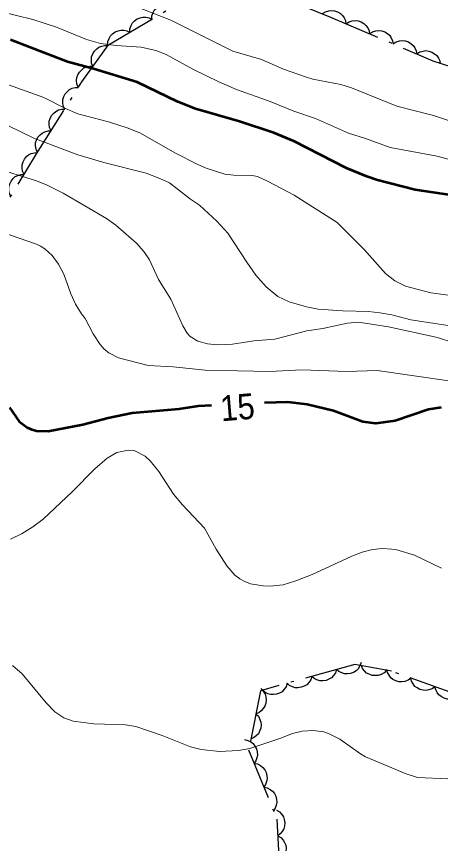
# Model space of a CAD drawing. Extents: x 356765 to 358572, y 5103174 to 5104650.
# Drawn here: x 357720.51 to 357745.32, y 5103497.3 to 5103545.71 of the extents above; entities that cross this region are included whole.
import ezdxf
from ezdxf.enums import TextEntityAlignment as Align

# ---------------------------------------------------------------- set-up
doc = ezdxf.new("R2010")
doc.units = 0
doc.header["$LTSCALE"] = 0.6
doc.linetypes.add('DOT_DASHED', pattern=[7.7, 5, -1.2, 0.3, -1.2])
for name, color, linetype, lineweight in [('1', 7, 'Continuous', 53), ('2', 7, 'Continuous', 13), ('44', 7, 'Continuous', 25)]:
    doc.layers.add(name, color=color, linetype=linetype, lineweight=lineweight)

msp = doc.modelspace()

# ---------------------------------------------------------------- linework, layer by layer
at = {"layer": '1'}
for points in [[(357748.85, 5103534.83), (357743.84, 5103535.57), (357741.64, 5103536.13), (357741.01, 5103536.34), (357739.82, 5103536.84), (357736.74, 5103538.42), (357735.57, 5103538.9), (357733.56, 5103539.57), (357730.98, 5103540.3), (357729.95, 5103540.71), (357727.56, 5103541.87), (357725.01, 5103542.65), (357723.49, 5103543.05), (357720.16, 5103544.34)], [(357745.37, 5103522.83), (357744.62, 5103522.7), (357742.67, 5103522.05), (357741.53, 5103521.88), (357740.78, 5103521.98), (357739.06, 5103522.63), (357737.51, 5103523), (357736.39, 5103523.13), (357735.02, 5103523.09)], [(357720.09, 5103522.83), (357720.65, 5103522.01), (357721.12, 5103521.65), (357721.4, 5103521.53), (357721.68, 5103521.45), (357722.36, 5103521.44), (357724.39, 5103521.82), (357725.86, 5103522.22), (357727.28, 5103522.51), (357730.02, 5103522.75), (357731.15, 5103522.93), (357731.92, 5103522.97)]]:
    msp.add_lwpolyline(points, dxfattribs=at)
at = {"layer": '2'}
for points in [[(357746.89, 5103539.26), (357744.92, 5103539.91), (357742.76, 5103540.46), (357740.11, 5103541.53), (357739.49, 5103541.74), (357737.84, 5103542.05), (357737.48, 5103542.16), (357736.14, 5103542.63), (357734.85, 5103543.19), (357733.17, 5103543.68), (357729.54, 5103545.5), (357726.78, 5103546.57)], [(357746.41, 5103537.18), (357745.12, 5103537.54), (357742.37, 5103538.05), (357740.94, 5103538.58), (357739.93, 5103538.88), (357738, 5103539.75), (357736.73, 5103540.17), (357735.35, 5103540.74), (357733.38, 5103541.43), (357732.35, 5103541.88), (357730.83, 5103542.63), (357729.27, 5103543.49), (357728.66, 5103543.73), (357727.8, 5103543.91), (357726.33, 5103544.01), (357725.42, 5103544.13), (357724.61, 5103544.36), (357722.85, 5103545.09), (357721.45, 5103545.54), (357719.55, 5103546)], [(357749.45, 5103528.92), (357744.75, 5103529.54), (357743.27, 5103529.93), (357742.64, 5103530.24), (357742.1, 5103530.66), (357740.86, 5103532.07), (357739.27, 5103533.65), (357736.75, 5103535.26), (357735.2, 5103536.08), (357734.61, 5103536.34), (357734.3, 5103536.4), (357733.23, 5103536.42), (357732.69, 5103536.49), (357731.61, 5103536.84), (357731.11, 5103537.05), (357729.81, 5103537.72), (357727.73, 5103538.91), (357726.99, 5103539.2), (357725.89, 5103539.54), (357724.1, 5103540.01), (357723.38, 5103540.32), (357722.11, 5103540.97), (357720.03, 5103541.72)], [(357746.93, 5103527.45), (357743.59, 5103527.96), (357742.47, 5103528.24), (357741.78, 5103528.36), (357741.1, 5103528.44), (357739.61, 5103528.48), (357738.16, 5103528.59), (357737.48, 5103528.72), (357736.46, 5103529.01), (357735.81, 5103529.32), (357735.11, 5103529.88), (357734.52, 5103530.58), (357733.98, 5103531.34), (357732.88, 5103533.03), (357732.23, 5103533.74), (357731.21, 5103534.67), (357730.69, 5103535.01), (357729.45, 5103535.97), (357728.9, 5103536.23), (357728.09, 5103536.54), (357725.61, 5103537.17), (357724.09, 5103537.61), (357721.52, 5103538.59), (357719.3, 5103539.67)], [(357746.11, 5103526.61), (357745.14, 5103526.92), (357742.28, 5103527.55), (357740.53, 5103527.82), (357739.87, 5103527.76), (357738.43, 5103527.45), (357737.5, 5103527.32), (357735.62, 5103526.82), (357734.4, 5103526.72), (357733.14, 5103526.54), (357732.29, 5103526.5), (357731.69, 5103526.55), (357731.12, 5103526.7), (357730.67, 5103526.99), (357730.5, 5103527.18), (357730.24, 5103527.61), (357729.53, 5103529.16), (357728.82, 5103530.32), (357728.28, 5103531.46), (357727.96, 5103531.95), (357727.53, 5103532.44), (357726.31, 5103533.5), (357725.77, 5103533.88), (357723.24, 5103535.37), (357722.29, 5103535.84), (357721.67, 5103536.09), (357719.14, 5103536.87)], [(357745.95, 5103524.37), (357741.61, 5103524.99), (357739.83, 5103524.93), (357737.2, 5103525.03), (357735.34, 5103524.94), (357731.55, 5103525.01), (357729.68, 5103525.2), (357728.21, 5103525.29), (357726.48, 5103525.73), (357725.9, 5103526.03), (357725.63, 5103526.24), (357725.41, 5103526.51), (357724.99, 5103527.13), (357724.52, 5103528.04), (357724.31, 5103528.3), (357723.96, 5103528.88), (357723.68, 5103529.48), (357723.28, 5103530.63), (357722.97, 5103531.21), (357722.6, 5103531.72), (357722.16, 5103532.11), (357721.91, 5103532.26), (357721.67, 5103532.38), (357719.64, 5103533.09)], [(357733.29, 5103513.01), (357733.04, 5103513.28), (357732.82, 5103513.55), (357732.19, 5103514.53), (357731.51, 5103515.76), (357730.22, 5103517.13), (357729.69, 5103517.76), (357728.83, 5103519.08), (357728.32, 5103519.71), (357728.03, 5103519.97), (357727.39, 5103520.3), (357727.06, 5103520.32), (357726.38, 5103520.19), (357725.81, 5103519.86), (357725.08, 5103519.24), (357723.77, 5103517.88), (357722.07, 5103516.29), (357721.45, 5103515.83), (357720.83, 5103515.45), (357720.15, 5103515.12)], [(357745.38, 5103513.42), (357743.8, 5103514.18), (357742.77, 5103514.5), (357742.47, 5103514.54), (357741.91, 5103514.58), (357741.34, 5103514.51), (357740.74, 5103514.36), (357740.13, 5103514.13), (357737.81, 5103513.04), (357736.85, 5103512.67), (357736.12, 5103512.45), (357735.36, 5103512.37), (357734.95, 5103512.38), (357734.2, 5103512.51), (357733.86, 5103512.63), (357733.57, 5103512.8), (357733.29, 5103513.01)], [(357745.76, 5103501.08), (357743.97, 5103501.17), (357743.31, 5103501.38), (357740.94, 5103502.38), (357740.63, 5103502.55), (357739.42, 5103503.41), (357738.81, 5103503.73), (357738.5, 5103503.83), (357737.86, 5103503.92), (357737.23, 5103503.87), (357736.65, 5103503.74), (357735.91, 5103503.44), (357734.17, 5103502.87), (357733.49, 5103502.74), (357732.39, 5103502.69), (357731.31, 5103502.8), (357730.68, 5103502.96), (357729.03, 5103503.63), (357727.49, 5103504.16), (357726.89, 5103504.25), (357725.02, 5103504.3), (357723.82, 5103504.46), (357723.27, 5103504.66), (357722.74, 5103505.01), (357722.24, 5103505.53), (357720.83, 5103507.23), (357720.27, 5103507.73)]]:
    msp.add_lwpolyline(points, dxfattribs=at)
at = {"layer": '44', "linetype": 'DOT_DASHED'}
for points in [[(357718.2, 5103531.95), (357721.68, 5103537.67), (357724.33, 5103541.89), (357725.88, 5103544.06), (357729.89, 5103546.42)], [(357736.33, 5103546.72), (357738.88, 5103545.68), (357744.88, 5103543.12), (357748.2, 5103542.05)], [(357746.38, 5103505.98), (357742.45, 5103507.39), (357740.31, 5103507.79), (357734.78, 5103506.24), (357734.09, 5103502.78), (357735.75, 5103498.72), (357735.91, 5103495.5)]]:
    msp.add_lwpolyline(points, dxfattribs=at)
at = {"layer": '44'}
for points in [[(357728.42, 5103545.55), (357728.43, 5103545.76), (357728.5, 5103545.95), (357728.58, 5103546.1), (357728.71, 5103546.22), (357728.86, 5103546.33), (357729.03, 5103546.4), (357729.19, 5103546.44), (357729.37, 5103546.43), (357729.55, 5103546.39), (357729.71, 5103546.32)], [(357738.41, 5103545.88), (357738.59, 5103545.99), (357738.78, 5103546.05), (357738.95, 5103546.07), (357739.12, 5103546.05), (357739.3, 5103545.99), (357739.46, 5103545.89), (357739.59, 5103545.78), (357739.68, 5103545.64), (357739.76, 5103545.47), (357739.79, 5103545.29)], [(357727.13, 5103544.79), (357727.14, 5103545), (357727.21, 5103545.19), (357727.29, 5103545.34), (357727.41, 5103545.46), (357727.56, 5103545.57), (357727.74, 5103545.64), (357727.9, 5103545.68), (357728.08, 5103545.67), (357728.26, 5103545.63), (357728.42, 5103545.55)], [(357739.79, 5103545.29), (357739.97, 5103545.4), (357740.16, 5103545.46), (357740.33, 5103545.48), (357740.5, 5103545.46), (357740.68, 5103545.4), (357740.84, 5103545.3), (357740.96, 5103545.19), (357741.06, 5103545.05), (357741.14, 5103544.88), (357741.17, 5103544.7)], [(357725.83, 5103544.03), (357725.85, 5103544.24), (357725.92, 5103544.43), (357726, 5103544.58), (357726.12, 5103544.7), (357726.27, 5103544.81), (357726.45, 5103544.88), (357726.61, 5103544.92), (357726.78, 5103544.91), (357726.96, 5103544.87), (357727.13, 5103544.79)], [(357741.17, 5103544.7), (357741.35, 5103544.82), (357741.54, 5103544.87), (357741.71, 5103544.89), (357741.88, 5103544.87), (357742.06, 5103544.81), (357742.22, 5103544.71), (357742.34, 5103544.61), (357742.44, 5103544.46), (357742.52, 5103544.29), (357742.55, 5103544.11)], [(357724.98, 5103542.8), (357724.9, 5103542.99), (357724.89, 5103543.19), (357724.9, 5103543.36), (357724.97, 5103543.52), (357725.06, 5103543.68), (357725.2, 5103543.82), (357725.32, 5103543.92), (357725.49, 5103543.98), (357725.67, 5103544.02), (357725.85, 5103544.02)], [(357742.55, 5103544.11), (357742.73, 5103544.23), (357742.92, 5103544.28), (357743.09, 5103544.31), (357743.26, 5103544.28), (357743.44, 5103544.22), (357743.6, 5103544.12), (357743.72, 5103544.02), (357743.82, 5103543.87), (357743.9, 5103543.7), (357743.93, 5103543.52)], [(357743.93, 5103543.52), (357744.11, 5103543.64), (357744.3, 5103543.69), (357744.47, 5103543.72), (357744.64, 5103543.69), (357744.82, 5103543.63), (357744.98, 5103543.53), (357745.1, 5103543.43), (357745.2, 5103543.28), (357745.28, 5103543.11), (357745.31, 5103542.94)], [(357724.11, 5103541.58), (357724.03, 5103541.77), (357724.02, 5103541.97), (357724.03, 5103542.14), (357724.09, 5103542.3), (357724.19, 5103542.46), (357724.32, 5103542.6), (357724.45, 5103542.7), (357724.62, 5103542.76), (357724.8, 5103542.8), (357724.98, 5103542.8)], [(357723.33, 5103540.29), (357723.24, 5103540.48), (357723.22, 5103540.68), (357723.22, 5103540.85), (357723.27, 5103541.02), (357723.36, 5103541.18), (357723.48, 5103541.33), (357723.6, 5103541.43), (357723.77, 5103541.51), (357723.94, 5103541.56), (357724.12, 5103541.56)], [(357722.53, 5103539.02), (357722.44, 5103539.21), (357722.42, 5103539.41), (357722.42, 5103539.58), (357722.47, 5103539.75), (357722.56, 5103539.91), (357722.69, 5103540.06), (357722.81, 5103540.16), (357722.97, 5103540.24), (357723.15, 5103540.29), (357723.33, 5103540.29)], [(357721.73, 5103537.75), (357721.65, 5103537.94), (357721.62, 5103538.14), (357721.62, 5103538.31), (357721.68, 5103538.48), (357721.76, 5103538.64), (357721.89, 5103538.78), (357722.01, 5103538.89), (357722.17, 5103538.97), (357722.35, 5103539.02), (357722.53, 5103539.02)], [(357720.95, 5103536.47), (357720.86, 5103536.66), (357720.84, 5103536.86), (357720.84, 5103537.03), (357720.89, 5103537.2), (357720.97, 5103537.36), (357721.09, 5103537.51), (357721.21, 5103537.62), (357721.37, 5103537.69), (357721.55, 5103537.74), (357721.73, 5103537.75)], [(357720.17, 5103535.19), (357720.08, 5103535.38), (357720.06, 5103535.58), (357720.06, 5103535.75), (357720.11, 5103535.91), (357720.19, 5103536.08), (357720.31, 5103536.22), (357720.43, 5103536.34), (357720.59, 5103536.41), (357720.77, 5103536.46), (357720.95, 5103536.47)], [(357740.68, 5103507.89), (357740.61, 5103507.7), (357740.5, 5103507.53), (357740.38, 5103507.41), (357740.23, 5103507.32), (357740.06, 5103507.25), (357739.87, 5103507.23), (357739.71, 5103507.23), (357739.54, 5103507.29), (357739.37, 5103507.37), (357739.24, 5103507.49)], [(357742.16, 5103507.44), (357742.02, 5103507.3), (357741.84, 5103507.2), (357741.68, 5103507.14), (357741.51, 5103507.13), (357741.32, 5103507.14), (357741.14, 5103507.21), (357741, 5103507.28), (357740.87, 5103507.41), (357740.76, 5103507.55), (357740.69, 5103507.72)], [(357739.24, 5103507.49), (357739.17, 5103507.29), (357739.05, 5103507.13), (357738.94, 5103507), (357738.79, 5103506.92), (357738.62, 5103506.85), (357738.43, 5103506.83), (357738.26, 5103506.83), (357738.09, 5103506.88), (357737.93, 5103506.97), (357737.79, 5103507.08)], [(357743.59, 5103506.98), (357743.42, 5103506.86), (357743.23, 5103506.79), (357743.06, 5103506.76), (357742.89, 5103506.77), (357742.71, 5103506.82), (357742.54, 5103506.91), (357742.41, 5103507.01), (357742.31, 5103507.15), (357742.22, 5103507.31), (357742.18, 5103507.49)], [(357736.35, 5103506.68), (357736.28, 5103506.48), (357736.16, 5103506.32), (357736.05, 5103506.19), (357735.9, 5103506.11), (357735.73, 5103506.04), (357735.54, 5103506.02), (357735.37, 5103506.02), (357735.21, 5103506.07), (357735.04, 5103506.16), (357734.9, 5103506.27)], [(357737.79, 5103507.08), (357737.73, 5103506.89), (357737.61, 5103506.72), (357737.5, 5103506.6), (357737.34, 5103506.51), (357737.17, 5103506.45), (357736.98, 5103506.42), (357736.82, 5103506.42), (357736.65, 5103506.48), (357736.49, 5103506.56), (357736.35, 5103506.68)], [(357745, 5103506.48), (357744.83, 5103506.35), (357744.64, 5103506.29), (357744.48, 5103506.25), (357744.3, 5103506.27), (357744.12, 5103506.31), (357743.96, 5103506.41), (357743.82, 5103506.5), (357743.72, 5103506.64), (357743.63, 5103506.81), (357743.59, 5103506.98)], [(357734.81, 5103506.37), (357734.95, 5103506.22), (357735.05, 5103506.04), (357735.1, 5103505.88), (357735.11, 5103505.71), (357735.09, 5103505.52), (357735.03, 5103505.34), (357734.95, 5103505.2), (357734.83, 5103505.07), (357734.68, 5103504.96), (357734.51, 5103504.89)], [(357746.41, 5103505.97), (357746.24, 5103505.85), (357746.05, 5103505.78), (357745.89, 5103505.75), (357745.71, 5103505.76), (357745.53, 5103505.81), (357745.37, 5103505.9), (357745.23, 5103506), (357745.13, 5103506.14), (357745.04, 5103506.3), (357745, 5103506.48)], [(357734.51, 5103504.89), (357734.66, 5103504.75), (357734.75, 5103504.57), (357734.81, 5103504.41), (357734.82, 5103504.24), (357734.8, 5103504.05), (357734.73, 5103503.87), (357734.66, 5103503.73), (357734.53, 5103503.6), (357734.38, 5103503.49), (357734.22, 5103503.42)], [(357733.84, 5103503.39), (357734.05, 5103503.34), (357734.22, 5103503.25), (357734.36, 5103503.15), (357734.46, 5103503.01), (357734.55, 5103502.84), (357734.59, 5103502.66), (357734.61, 5103502.5), (357734.57, 5103502.32), (357734.51, 5103502.15), (357734.41, 5103502)], [(357734.41, 5103502), (357734.61, 5103501.96), (357734.79, 5103501.86), (357734.92, 5103501.76), (357735.03, 5103501.62), (357735.12, 5103501.46), (357735.16, 5103501.27), (357735.18, 5103501.11), (357735.14, 5103500.93), (357735.08, 5103500.76), (357734.98, 5103500.61)], [(357734.98, 5103500.61), (357735.18, 5103500.57), (357735.36, 5103500.47), (357735.49, 5103500.37), (357735.6, 5103500.23), (357735.68, 5103500.07), (357735.72, 5103499.88), (357735.74, 5103499.72), (357735.71, 5103499.55), (357735.64, 5103499.37), (357735.54, 5103499.22)], [(357735.72, 5103499.26), (357735.9, 5103499.15), (357736.04, 5103499), (357736.13, 5103498.87), (357736.18, 5103498.7), (357736.21, 5103498.52), (357736.19, 5103498.32), (357736.15, 5103498.17), (357736.06, 5103498.01), (357735.94, 5103497.87), (357735.8, 5103497.76)], [(357735.8, 5103497.76), (357735.98, 5103497.66), (357736.11, 5103497.5), (357736.2, 5103497.37), (357736.26, 5103497.2), (357736.28, 5103497.02), (357736.26, 5103496.83), (357736.22, 5103496.67), (357736.13, 5103496.52), (357736.02, 5103496.37), (357735.87, 5103496.27)]]:
    msp.add_lwpolyline(points, dxfattribs=at)

# ---------------------------------------------------------------- texts
at = {"layer": '1', "width": 0.9}
msp.add_text('15', height=1.5, rotation=4.81, dxfattribs=at).set_placement((357733.4971, 5103522.0964), align=Align.CENTER)

doc.saveas('drawing.dxf')
